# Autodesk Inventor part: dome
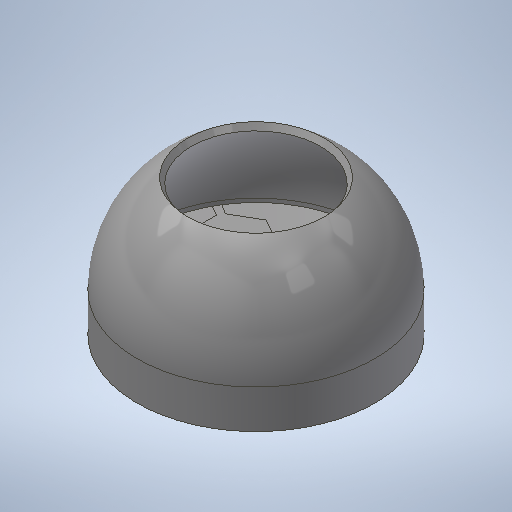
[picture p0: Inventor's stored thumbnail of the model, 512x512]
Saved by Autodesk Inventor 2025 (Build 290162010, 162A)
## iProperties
Created: 2025-02
Part Number: dome
Material: 1.0037 S235JR
Document SubType Name: Modeling
Designer: BennF
Density: 7.85 g/cm^3
Appearance: Stahl
Author: BennF
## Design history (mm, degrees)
sketch "Sketch2"
  geometry: L1 (-20.5, 20.404)-(20.5, 20.404); L2 (20.5, 20.404)-(20.5, -20.404); L3 (20.5, -20.404)-(-20.5, -20.404); L4 (-20.5, -20.404)-(-20.5, 20.404); L5 (-16.973, 10.58)-(-15.176, 9.46); L6 (16.973, 10.58)-(15.176, 9.46); L7 (0, 18.244)-(15.176, 9.46); L8 (-15.176, 9.46)-(-10.355, 12.251); L9 (0, 18.244)-(-5.177, 15.248); L10 (-10.355, 12.251)-(-7.309, 10.504); L11 (-5.177, 15.248)-(-2.864, 13.925); L12 (-0.676, -19.989)-(-0.604, -17.873); L13 (-0.604, -17.873)-(-5.432, -15.093); L14 (-5.432, -15.093)-(-5.442, -11.582); L15 (-10.617, -12.107)-(-10.627, -9.443); L16 (-15.8, -9.122)-(-10.617, -12.107); L17 (-15.8, -9.122)-(-15.781, 8.413); L18 (-17.649, 9.409)-(-15.781, 8.413); L19 (17.649, 9.409)-(15.781, 8.413); L20 (15.781, 8.413)-(15.787, 2.842); L21 (15.787, 2.842)-(12.751, 1.078); L22 (15.794, -3.141)-(13.492, -4.482); L23 (15.8, -9.122)-(15.794, -3.141); L24 (15.8, -9.122)-(0.604, -17.873); L25 (0.676, -19.989)-(0.604, -17.873); A1 r 20 centre (0, 0) between (16.973, 10.58) and (-16.973, 10.58); A2 r 20 centre (0, 0) between (-17.649, 9.409) and (-0.676, -19.989); A3 r 20 centre (0, 0) between (0.676, -19.989) and (17.649, 9.409); 7 further points; 4 other entities
  constraints: 48 end point, 6 point on circle, 3 centre point, 3 coincident, 3 midpoint, 3 vertical alignment, 2 line through centre, 1 collinear, 1 equal length, 1 horizontal alignment, 73 other
  dimensions: "d5" = 41 distance of L1.start L1.end; "d15" = 20 radius of A1; "d27" = 118 deg angle of L6 L7; "d30" = 118 deg angle of L8 L5 (= d27); "d85" = 360 deg dimension on A1.centre L6.start (derived)
  node "Image1"
  node "Sketch Circular Pattern1" dims "d85" = 360 deg (derived)
extrude "Extrusion1" new body sketch "Sketch2" distance "d79" = 5; taper "d80" = 0 deg
extrude "Extrusion2" new body sketch "Sketch2" stored distance "d88" = 5; taper "d89" = 0 deg
extrude "Extrusion3" new body sketch "Sketch2" stored distance "d91" = 10; taper "d92" = 0 deg
sketch "Sketch3"
  geometry: L1 (15.781, 8.413)-(17.649, 9.409) reference; L2 (15.8, -9.122)-(15.781, 8.413) reference; L3 (10.617, -12.107)-(15.8, -9.122) reference; L4 (10.627, -9.443)-(10.617, -12.107) reference; L5 (5.432, -15.093)-(5.442, -11.582) reference; L6 (0.604, -17.873)-(5.432, -15.093) reference; L7 (0.676, -19.989)-(0.604, -17.873) reference; L8 (-0.604, -17.873)-(-0.676, -19.989) reference; L9 (-15.8, -9.122)-(-0.604, -17.873) reference; L10 (-15.794, -3.141)-(-15.8, -9.122) reference; L11 (-13.492, -4.482)-(-15.794, -3.141) reference; L12 (-15.787, 2.842)-(-12.751, 1.078) reference; L13 (-15.781, 8.413)-(-15.787, 2.842) reference; L14 (-17.649, 9.409)-(-15.781, 8.413) reference; L15 (-15.176, 9.46)-(-16.973, 10.58) reference; L16 (0, 18.244)-(-15.176, 9.46) reference; L17 (5.177, 15.248)-(0, 18.244) reference; L18 (2.864, 13.925)-(5.177, 15.248) reference; L19 (10.355, 12.251)-(7.309, 10.504) reference; L20 (15.176, 9.46)-(10.355, 12.251) reference; L21 (16.973, 10.58)-(15.176, 9.46) reference; A1 r 20 centre (0, 0) between (0.676, -19.989) and (17.649, 9.409) reference; A2 r 20 centre (0, 0) between (0.676, -19.989) and (17.649, 9.409) reference; A3 r 20 centre (0, 0) between (-17.649, 9.409) and (-0.676, -19.989) reference; A4 r 20 centre (0, 0) between (16.973, 10.58) and (-16.973, 10.58) reference; 11 further points; 3 other entities
  constraints: 1 coincident, 6 other
extrude "Extrusion4" new body sketch "Sketch3" stored distance "d93" = 10; taper "d94" = 0 deg
sketch "Sketch4"
  geometry: L1 (18, -1)-(21, -1); L2 (21, -1)-(21, 5); L3 (0, 0)-(0, 5) reference; L4 (0, 0)-(0, 5); L5 (18, -1)-(18, -2.2); L6 (18, -2.2)-(22.2, -2.2); L7 (22.2, -2.2)-(22.2, 5); L8 (12.733, 23.185)-(12.045, 22.202); L9 (20, 0)-(0.676, 0) reference; L10 (0, 5)-(11.758, 21.793); A1 r 21 centre (0, 5) between (21, 5) and (12.045, 22.202); A2 r 22.2 centre (0, 5) between (22.2, 5) and (12.733, 23.185); 1 further point
  constraints: 16 end point, 4 point on circle, 3 vertical, 2 centre point, 2 coincident, 2 horizontal, 2 horizontal alignment, 1 collinear, 1 perpendicular, 1 tangent
  dimensions: "d95" = 21 radius of A1; "d96" = 1.2 radial gap between concentric circles of A1 A2; "d97" = 1 distance between parallel lines of L9 L1; "d98" = 3 distance of L1.start L1.end; "d100" = 1.2 distance of L1.start L5.end (= d96); "d101" = 145 deg angle of L3 L10
revolve "Revolution1" sketch "Sketch4" stored, may be unused: angle "d99" = 90 deg
body "Solid1"
body "Solid2"
body "Solid3"
node "Projected Loop1"
node "Projected Loop2"
node "Projected Loop3"
body "Solid4"
body "Solid5"
